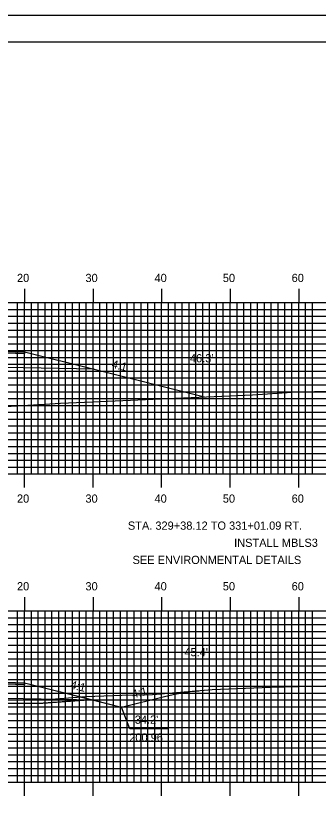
# Model space of a CAD drawing. Extents: x 1821998 to 1822342, y 442591 to 442811.
# Drawn here: x 1822183 to 1822227.1, y 442696.2 to 442810.5 of the extents above; entities that cross this region are included whole.
import ezdxf

# ---------------------------------------------------------------- set-up
doc = ezdxf.new("R2010")
doc.units = 0
for name, color, linetype in [('ANNOTATION', 7, 'Continuous'), ('BORDER', 7, 'Continuous'), ('D_Roadway_Centerline', 7, 'Continuous'), ('D_Roadway_Edge_Shoulder', 7, 'Continuous'), ('D_Roadway_SlopeLines', 7, 'Continuous'), ('D_Roadway_SubGrade', 7, 'Continuous'), ('D_Text_Standard', 7, 'Continuous'), ('GRUBBING IN FILL', 7, 'Continuous'), ('H_V ANNOTATION', 7, 'Continuous'), ('MAJOR', 7, 'Continuous'), ('MINOR', 7, 'Continuous'), ('PLOT BOUNDARY', 7, 'Continuous'), ('S_Roadway_Centerline', 7, 'Continuous')]:
    doc.layers.add(name, color=color, linetype=linetype)

msp = doc.modelspace()

# ---------------------------------------------------------------- linework, layer by layer
at = {"layer": 'ANNOTATION'}
msp.add_lwpolyline([(1822205.31, 442706.48), (1822199.62, 442706.48), (1822198.43, 442709.63)], dxfattribs=at)
at = {"layer": 'BORDER'}
msp.add_lwpolyline([(1822014.66, 442596.67), (1822334.66, 442596.67), (1822334.66, 442806.67), (1822014.66, 442806.67)], close=True, dxfattribs=at)
at = {"layer": 'D_Roadway_Centerline'}
for points in [[(1822109.99, 442752.45), (1822127.87, 442758.41), (1822129.62, 442758.85), (1822139.87, 442761.41), (1822146.99, 442761.69), (1822164.26, 442762.04), (1822176.26, 442761.8), (1822184.26, 442761.48), (1822194.43, 442758.94), (1822210.54, 442754.91)], [(1822108.66, 442704.58), (1822125.09, 442710.05), (1822126.79, 442710.48), (1822137.09, 442713.05), (1822143.66, 442713.32), (1822164.26, 442713.73), (1822176.26, 442713.49), (1822184.26, 442713.17), (1822194.43, 442710.63), (1822198.43, 442709.63), (1822204.69, 442711.19), (1822205.94, 442711.48), (1822207.19, 442711.71), (1822208.44, 442711.89), (1822209.69, 442712.02)]]:
    msp.add_lwpolyline(points, dxfattribs=at)
at = {"layer": 'D_Roadway_Edge_Shoulder'}
for points in [[(1822176.26, 442761.8), (1822184.26, 442761.48), (1822184.26, 442761.23), (1822176.26, 442761.55)], [(1822176.26, 442713.49), (1822184.26, 442713.17), (1822184.26, 442712.92), (1822176.26, 442713.24)]]:
    msp.add_lwpolyline(points, close=True, dxfattribs=at)
at = {"layer": 'D_Roadway_SlopeLines'}
for points in [[(1822184.26, 442761.48), (1822194.43, 442758.94), (1822210.54, 442754.91)], [(1822184.26, 442713.17), (1822198.43, 442709.63)], [(1822198.43, 442709.63), (1822204.69, 442711.19), (1822205.94, 442711.48), (1822207.19, 442711.71), (1822208.44, 442711.89), (1822209.69, 442712.02)]]:
    msp.add_lwpolyline(points, dxfattribs=at)
at = {"layer": 'D_Roadway_SubGrade'}
for points in [[(1822146.99, 442759.19), (1822129.62, 442758.85), (1822139.87, 442761.41), (1822139.87, 442761.16), (1822146.99, 442761.44), (1822164.26, 442761.79), (1822176.26, 442761.55), (1822184.26, 442761.23), (1822184.26, 442761.48), (1822194.43, 442758.94), (1822176.26, 442759.3), (1822164.26, 442759.54)], [(1822143.66, 442710.82), (1822126.79, 442710.48), (1822137.09, 442713.05), (1822137.09, 442712.8), (1822143.66, 442713.07), (1822164.26, 442713.48), (1822176.26, 442713.24), (1822184.26, 442712.92), (1822184.26, 442713.17), (1822194.43, 442710.63), (1822176.26, 442710.99), (1822164.26, 442711.23)]]:
    msp.add_lwpolyline(points, close=True, dxfattribs=at)
at = {"layer": 'GRUBBING IN FILL'}
msp.add_lwpolyline([(1822126.79, 442704.82), (1822135.16, 442705.37), (1822151.14, 442707.08), (1822154.61, 442707.35), (1822160.26, 442708.12), (1822163.8, 442708.4), (1822170.35, 442709.02), (1822181.73, 442710.2), (1822186.27, 442710.15), (1822192.98, 442710.65)], dxfattribs=at)
msp.add_lwpolyline([(1822126.79, 442704.82), (1822135.16, 442705.37), (1822151.14, 442707.08), (1822154.61, 442707.35), (1822160.26, 442708.12), (1822163.8, 442708.4), (1822170.35, 442709.02), (1822181.73, 442710.2), (1822186.27, 442710.15), (1822192.98, 442710.65)], dxfattribs=at)
msp.add_lwpolyline([(1822164.26, 442708.94), (1822167.03, 442709.2), (1822170.3, 442709.51), (1822176, 442710.11), (1822181.71, 442710.7), (1822183.98, 442710.68), (1822186.26, 442710.65), (1822187.71, 442710.76), (1822192.98, 442710.65), (1822189.12, 442710.36), (1822186.27, 442710.15), (1822184, 442710.18), (1822181.73, 442710.2), (1822176.04, 442709.61), (1822170.35, 442709.02), (1822164.26, 442708.44)], close=True, dxfattribs=at)
msp.add_lwpolyline([(1822164.26, 442708.94), (1822167.03, 442709.2), (1822170.3, 442709.51), (1822176, 442710.11), (1822181.71, 442710.7), (1822183.98, 442710.68), (1822186.26, 442710.65), (1822187.71, 442710.76), (1822192.98, 442710.65), (1822189.12, 442710.36), (1822186.27, 442710.15), (1822184, 442710.18), (1822181.73, 442710.2), (1822176.04, 442709.61), (1822170.35, 442709.02), (1822164.26, 442708.44)], close=True, dxfattribs=at)
at = {"layer": 'MAJOR'}
for p, q in [((1822184.26, 442770.67), (1822184.26, 442768.67)), ((1822194.26, 442770.67), (1822194.26, 442768.67)), ((1822204.26, 442770.67), (1822204.26, 442768.67)), ((1822214.26, 442770.67), (1822214.26, 442768.67)), ((1822224.26, 442770.67), (1822224.26, 442768.67)), ((1822024.26, 442768.67), (1822304.26, 442768.67)), ((1822024.26, 442768.67), (1822304.26, 442768.67)), ((1822184.26, 442743.67), (1822184.26, 442768.67)), ((1822194.26, 442743.67), (1822194.26, 442768.67)), ((1822204.26, 442743.67), (1822204.26, 442768.67)), ((1822214.26, 442743.67), (1822214.26, 442768.67)), ((1822224.26, 442743.67), (1822224.26, 442768.67)), ((1822024.26, 442763.67), (1822304.26, 442763.67)), ((1822024.26, 442758.67), (1822304.26, 442758.67)), ((1822024.26, 442753.67), (1822304.26, 442753.67)), ((1822024.26, 442748.67), (1822304.26, 442748.67)), ((1822024.26, 442743.67), (1822304.26, 442743.67)), ((1822024.26, 442743.67), (1822304.26, 442743.67)), ((1822184.26, 442741.66), (1822184.26, 442743.67)), ((1822194.26, 442741.66), (1822194.26, 442743.67)), ((1822204.26, 442741.66), (1822204.26, 442743.67)), ((1822214.26, 442741.66), (1822214.26, 442743.67)), ((1822224.26, 442741.66), (1822224.26, 442743.67)), ((1822184.26, 442725.67), (1822184.26, 442723.67)), ((1822194.26, 442725.67), (1822194.26, 442723.67)), ((1822204.26, 442725.67), (1822204.26, 442723.67)), ((1822214.26, 442725.67), (1822214.26, 442723.67)), ((1822224.26, 442725.67), (1822224.26, 442723.67)), ((1822024.26, 442723.67), (1822304.26, 442723.67)), ((1822024.26, 442723.67), (1822304.26, 442723.67)), ((1822184.26, 442698.67), (1822184.26, 442723.67)), ((1822194.26, 442698.67), (1822194.26, 442723.67)), ((1822204.26, 442698.67), (1822204.26, 442723.67)), ((1822214.26, 442698.67), (1822214.26, 442723.67)), ((1822224.26, 442698.67), (1822224.26, 442723.67)), ((1822024.26, 442718.67), (1822304.26, 442718.67)), ((1822024.26, 442713.67), (1822304.26, 442713.67)), ((1822024.26, 442708.67), (1822304.26, 442708.67)), ((1822024.26, 442703.67), (1822304.26, 442703.67)), ((1822024.26, 442698.67), (1822304.26, 442698.67)), ((1822024.26, 442698.67), (1822304.26, 442698.67)), ((1822184.26, 442696.66), (1822184.26, 442698.67)), ((1822194.26, 442696.66), (1822194.26, 442698.67)), ((1822204.26, 442696.66), (1822204.26, 442698.67)), ((1822214.26, 442696.66), (1822214.26, 442698.67)), ((1822224.26, 442696.66), (1822224.26, 442698.67))]:
    msp.add_line(p, q, dxfattribs=at)
at = {"layer": 'MINOR'}
for p, q in [((1822024.26, 442767.67), (1822304.26, 442767.67)), ((1822183.26, 442743.67), (1822183.26, 442768.67)), ((1822185.26, 442743.67), (1822185.26, 442768.67)), ((1822186.26, 442743.67), (1822186.26, 442768.67)), ((1822187.26, 442743.67), (1822187.26, 442768.67)), ((1822188.26, 442743.67), (1822188.26, 442768.67)), ((1822189.26, 442743.67), (1822189.26, 442768.67)), ((1822190.26, 442743.67), (1822190.26, 442768.67)), ((1822191.26, 442743.67), (1822191.26, 442768.67)), ((1822192.26, 442743.67), (1822192.26, 442768.67)), ((1822193.26, 442743.67), (1822193.26, 442768.67)), ((1822195.26, 442743.67), (1822195.26, 442768.67)), ((1822196.26, 442743.67), (1822196.26, 442768.67)), ((1822197.26, 442743.67), (1822197.26, 442768.67)), ((1822198.26, 442743.67), (1822198.26, 442768.67)), ((1822199.26, 442743.67), (1822199.26, 442768.67)), ((1822200.26, 442743.67), (1822200.26, 442768.67)), ((1822201.26, 442743.67), (1822201.26, 442768.67)), ((1822202.26, 442743.67), (1822202.26, 442768.67)), ((1822203.26, 442743.67), (1822203.26, 442768.67)), ((1822205.26, 442743.67), (1822205.26, 442768.67)), ((1822206.26, 442743.67), (1822206.26, 442768.67)), ((1822207.26, 442743.67), (1822207.26, 442768.67)), ((1822208.26, 442743.67), (1822208.26, 442768.67)), ((1822209.26, 442743.67), (1822209.26, 442768.67)), ((1822210.26, 442743.67), (1822210.26, 442768.67)), ((1822211.26, 442743.67), (1822211.26, 442768.67)), ((1822212.26, 442743.67), (1822212.26, 442768.67)), ((1822213.26, 442743.67), (1822213.26, 442768.67)), ((1822215.26, 442743.67), (1822215.26, 442768.67)), ((1822216.26, 442743.67), (1822216.26, 442768.67)), ((1822217.26, 442743.67), (1822217.26, 442768.67)), ((1822218.26, 442743.67), (1822218.26, 442768.67)), ((1822219.26, 442743.67), (1822219.26, 442768.67)), ((1822220.26, 442743.67), (1822220.26, 442768.67)), ((1822221.26, 442743.67), (1822221.26, 442768.67)), ((1822222.26, 442743.67), (1822222.26, 442768.67)), ((1822223.26, 442743.67), (1822223.26, 442768.67)), ((1822225.26, 442743.67), (1822225.26, 442768.67)), ((1822226.26, 442743.67), (1822226.26, 442768.67)), ((1822024.26, 442766.67), (1822304.26, 442766.67)), ((1822024.26, 442765.67), (1822304.26, 442765.67)), ((1822024.26, 442764.67), (1822304.26, 442764.67)), ((1822024.26, 442762.67), (1822304.26, 442762.67)), ((1822024.26, 442761.67), (1822304.26, 442761.67)), ((1822024.26, 442760.67), (1822304.26, 442760.67)), ((1822024.26, 442759.67), (1822304.26, 442759.67)), ((1822024.26, 442757.67), (1822304.26, 442757.67)), ((1822024.26, 442756.67), (1822304.26, 442756.67)), ((1822024.26, 442755.67), (1822304.26, 442755.67)), ((1822024.26, 442754.67), (1822304.26, 442754.67)), ((1822024.26, 442752.67), (1822304.26, 442752.67)), ((1822024.26, 442751.67), (1822304.26, 442751.67)), ((1822024.26, 442750.67), (1822304.26, 442750.67)), ((1822024.26, 442749.67), (1822304.26, 442749.67)), ((1822024.26, 442747.67), (1822304.26, 442747.67)), ((1822024.26, 442746.67), (1822304.26, 442746.67)), ((1822024.26, 442745.67), (1822304.26, 442745.67)), ((1822024.26, 442744.67), (1822304.26, 442744.67)), ((1822183.26, 442698.67), (1822183.26, 442723.67)), ((1822185.26, 442698.67), (1822185.26, 442723.67)), ((1822186.26, 442698.67), (1822186.26, 442723.67)), ((1822187.26, 442698.67), (1822187.26, 442723.67)), ((1822188.26, 442698.67), (1822188.26, 442723.67)), ((1822189.26, 442698.67), (1822189.26, 442723.67)), ((1822190.26, 442698.67), (1822190.26, 442723.67)), ((1822191.26, 442698.67), (1822191.26, 442723.67)), ((1822192.26, 442698.67), (1822192.26, 442723.67)), ((1822193.26, 442698.67), (1822193.26, 442723.67)), ((1822195.26, 442698.67), (1822195.26, 442723.67)), ((1822196.26, 442698.67), (1822196.26, 442723.67)), ((1822197.26, 442698.67), (1822197.26, 442723.67)), ((1822198.26, 442698.67), (1822198.26, 442723.67)), ((1822199.26, 442698.67), (1822199.26, 442723.67)), ((1822200.26, 442698.67), (1822200.26, 442723.67)), ((1822201.26, 442698.67), (1822201.26, 442723.67)), ((1822202.26, 442698.67), (1822202.26, 442723.67)), ((1822203.26, 442698.67), (1822203.26, 442723.67)), ((1822205.26, 442698.67), (1822205.26, 442723.67)), ((1822206.26, 442698.67), (1822206.26, 442723.67)), ((1822207.26, 442698.67), (1822207.26, 442723.67)), ((1822208.26, 442698.67), (1822208.26, 442723.67)), ((1822209.26, 442698.67), (1822209.26, 442723.67)), ((1822210.26, 442698.67), (1822210.26, 442723.67)), ((1822211.26, 442698.67), (1822211.26, 442723.67)), ((1822212.26, 442698.67), (1822212.26, 442723.67)), ((1822213.26, 442698.67), (1822213.26, 442723.67)), ((1822215.26, 442698.67), (1822215.26, 442723.67)), ((1822216.26, 442698.67), (1822216.26, 442723.67)), ((1822217.26, 442698.67), (1822217.26, 442723.67)), ((1822218.26, 442698.67), (1822218.26, 442723.67)), ((1822219.26, 442698.67), (1822219.26, 442723.67)), ((1822220.26, 442698.67), (1822220.26, 442723.67)), ((1822221.26, 442698.67), (1822221.26, 442723.67)), ((1822222.26, 442698.67), (1822222.26, 442723.67)), ((1822223.26, 442698.67), (1822223.26, 442723.67)), ((1822225.26, 442698.67), (1822225.26, 442723.67)), ((1822226.26, 442698.67), (1822226.26, 442723.67)), ((1822024.26, 442722.67), (1822304.26, 442722.67)), ((1822024.26, 442721.67), (1822304.26, 442721.67)), ((1822024.26, 442720.67), (1822304.26, 442720.67)), ((1822024.26, 442719.67), (1822304.26, 442719.67)), ((1822024.26, 442717.67), (1822304.26, 442717.67)), ((1822024.26, 442716.67), (1822304.26, 442716.67)), ((1822024.26, 442715.67), (1822304.26, 442715.67)), ((1822024.26, 442714.67), (1822304.26, 442714.67)), ((1822024.26, 442712.67), (1822304.26, 442712.67)), ((1822024.26, 442711.67), (1822304.26, 442711.67)), ((1822024.26, 442710.67), (1822304.26, 442710.67)), ((1822024.26, 442709.67), (1822304.26, 442709.67)), ((1822024.26, 442707.67), (1822304.26, 442707.67)), ((1822024.26, 442706.67), (1822304.26, 442706.67)), ((1822024.26, 442705.67), (1822304.26, 442705.67)), ((1822024.26, 442704.67), (1822304.26, 442704.67)), ((1822024.26, 442702.67), (1822304.26, 442702.67)), ((1822024.26, 442701.67), (1822304.26, 442701.67)), ((1822024.26, 442700.67), (1822304.26, 442700.67)), ((1822024.26, 442699.67), (1822304.26, 442699.67))]:
    msp.add_line(p, q, dxfattribs=at)
at = {"layer": 'PLOT BOUNDARY'}
msp.add_lwpolyline([(1821998.47, 442590.55), (1822338.47, 442590.55), (1822338.47, 442810.55), (1821998.47, 442810.55)], close=True, dxfattribs=at)
at = {"layer": 'S_Roadway_Centerline'}
for points in [[(1822096.56, 442752.9), (1822105.84, 442752.59), (1822107, 442752.63), (1822111.32, 442752.37), (1822118.63, 442752.11), (1822122.29, 442751.99), (1822133.52, 442752.41), (1822139.13, 442752.27), (1822148.35, 442752.53), (1822156.06, 442752.71), (1822171.39, 442753.04), (1822172.93, 442753.09), (1822177.45, 442753.28), (1822187.17, 442753.85), (1822189.53, 442753.97), (1822194.17, 442754.19), (1822206.35, 442754.73), (1822217.52, 442755.2), (1822223.32, 442755.6), (1822226.56, 442755.71), (1822241.04, 442756.07)], [(1822103.88, 442704.49), (1822115.53, 442704.7), (1822118.02, 442704.79), (1822118.53, 442704.8), (1822119.46, 442704.83), (1822135.11, 442705.87), (1822151.09, 442707.58), (1822154.56, 442707.84), (1822160.21, 442708.62), (1822163.76, 442708.9), (1822170.3, 442709.51), (1822181.71, 442710.7), (1822186.26, 442710.65), (1822193.2, 442711.17), (1822198.44, 442711.36), (1822202.91, 442711.46), (1822211.65, 442712.18), (1822220.15, 442712.54), (1822234.11, 442712.9)]]:
    msp.add_lwpolyline(points, dxfattribs=at)

# ---------------------------------------------------------------- texts
at = {"layer": 'ANNOTATION'}
for rotation, p in [(345.9638, (1822196.9, 442759.18)), (345.9638, (1822190.85, 442712.38)), (14.0362, (1822200.1, 442710.9))]:
    msp.add_text('4:1', height=1.2, rotation=rotation, dxfattribs=at).set_placement(p)
for s, p in [("34.2'", (1822200.35, 442707.2)), ('200.96', (1822199.54, 442704.6))]:
    msp.add_text(s, height=1.2, dxfattribs=at).set_placement(p)
at = {"layer": 'D_Text_Standard'}
for s, p in [("46.3'", (1822208.39, 442759.95)), ('STA. 329+38.12 TO 331+01.09 RT.', (1822199.34, 442735.52)), ('INSTALL MBLS3', (1822214.84, 442733.02)), ('SEE ENVIRONMENTAL DETAILS', (1822200.02, 442730.52)), ("45.4'", (1822207.58, 442717.06))]:
    msp.add_text(s, height=1.2, dxfattribs=at).set_placement(p)
at = {"layer": 'H_V ANNOTATION'}
for s, p in [('20', (1822183.16, 442771.67)), ('30', (1822193.15, 442771.67)), ('40', (1822203.23, 442771.67)), ('50', (1822213.19, 442771.67)), ('60', (1822223.23, 442771.67)), ('20', (1822183.16, 442739.47)), ('30', (1822193.15, 442739.47)), ('40', (1822203.23, 442739.47)), ('50', (1822213.19, 442739.47)), ('60', (1822223.23, 442739.47)), ('20', (1822183.16, 442726.67)), ('30', (1822193.15, 442726.67)), ('40', (1822203.23, 442726.67)), ('50', (1822213.19, 442726.67)), ('60', (1822223.23, 442726.67))]:
    msp.add_text(s, height=1.2, dxfattribs=at).set_placement(p)

doc.saveas('drawing.dxf')
